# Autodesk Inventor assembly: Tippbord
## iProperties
Created: 2001-12
Part Number: Tippbord
Document SubType Name: Assembly
Designer: Tobben
Control State: 0
Master: False
Checked Out: False
Shininess: 64.0
Length Units: 11269
Angle Units: 11279
Time Units: 11290
Mass Units: 11283
Length Display Precision: 3
Angle Display Precision: 2
Density: 0.0
Volumn: 0.0
Area: 0.0
PropertySet Name: Model Information
Author: Tobben
